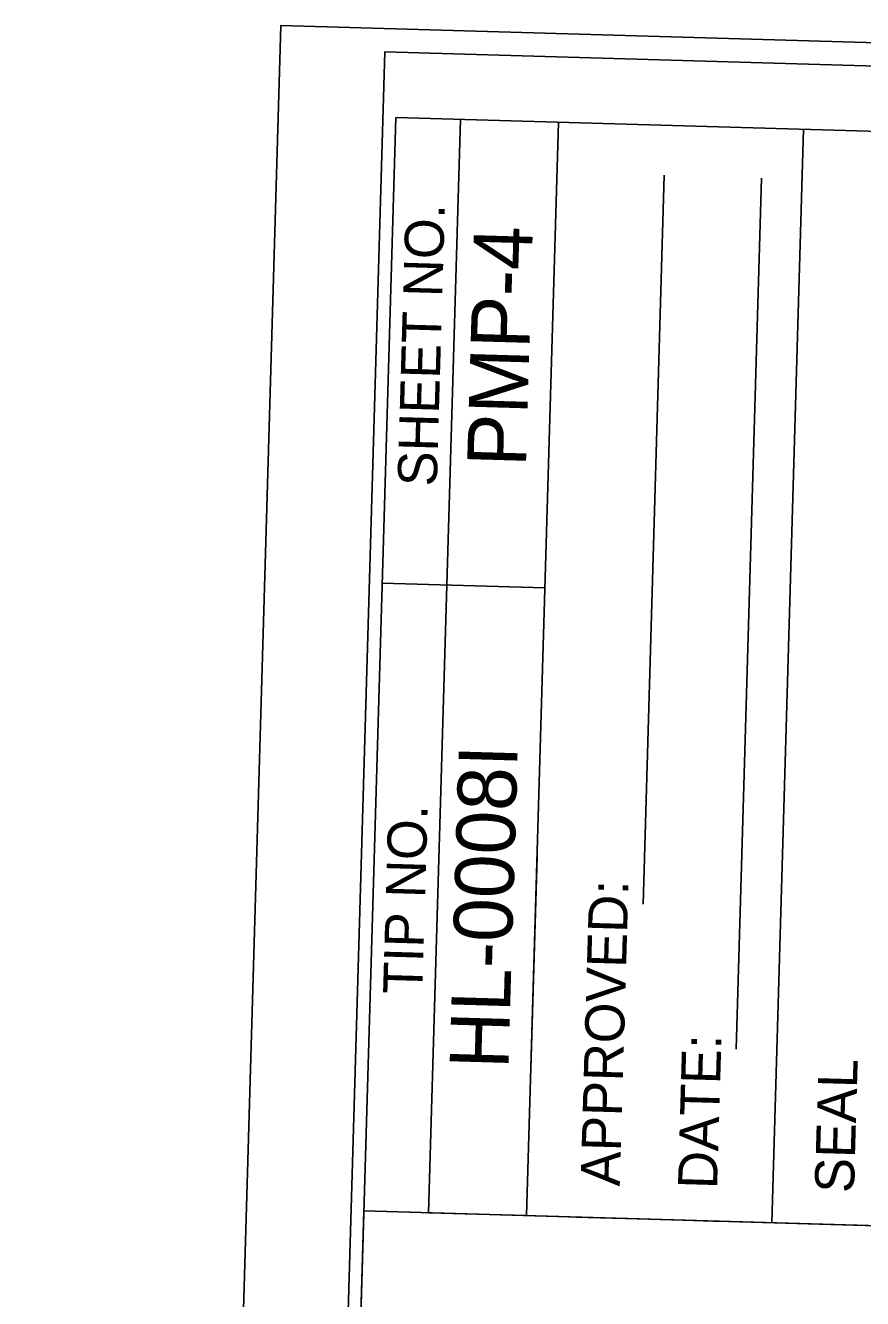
# Model space of a CAD drawing. Extents: x 2097002 to 2098146, y 685127 to 687089.
# Drawn here: x 2097002.1 to 2097162.3, y 686598.1 to 686842 of the extents above; entities that cross this region are included whole.
import ezdxf

# ---------------------------------------------------------------- set-up
doc = ezdxf.new("R2010")
doc.units = 0
for name, color, linetype in [('Sheet Data Field CELL', 7, 'Continuous'), ('Sheet Layout Plan Border', 7, 'Continuous'), ('Sheet Plan CELL', 7, 'Continuous'), ('Sheet Plot Border Inside CELL', 7, 'Continuous'), ('Sheet Plot Border Outside CELL', 7, 'Continuous'), ('Sheet Title CELL', 7, 'Continuous')]:
    doc.layers.add(name, color=color, linetype=linetype)

msp = doc.modelspace()

# ---------------------------------------------------------------- linework, layer by layer
at = {"layer": 'Sheet Layout Plan Border'}
msp.add_lwpolyline([(2098110.68, 686386.52), (2098090.85, 685704.42), (2097236.93, 685318.96), (2097029.37, 685324.99), (2097061.33, 686424.42), (2097062.77, 686473.85), (2097066.87, 686614.87), (2097306.86, 686607.89), (2097310.43, 686730.69), (2098032.53, 686709.7), (2098023.21, 686389.06)], close=True, dxfattribs=at)
at = {"layer": 'Sheet Plan CELL'}
for p, q in [((2097072.96, 686824.36), (2097029.37, 685324.98)), ((2098122.52, 686793.84), (2097072.96, 686824.36))]:
    msp.add_line(p, q, dxfattribs=at)
at = {"layer": 'Sheet Plot Border Inside CELL'}
msp.add_lwpolyline([(2098076.98, 685140.97), (2098125.38, 686806.22), (2097070.84, 686836.88), (2097022.43, 685171.63)], close=True, dxfattribs=at)
at = {"layer": 'Sheet Plot Border Outside CELL'}
msp.add_lwpolyline([(2098096.59, 685127.4), (2098145.51, 686810.14), (2097050.98, 686841.96), (2097002.06, 685159.22)], close=True, dxfattribs=at)
at = {"layer": 'Sheet Title CELL'}
for p, q in [((2097082.75, 686734.77), (2097085.34, 686824)), ((2097104.11, 686823.45), (2097098.02, 686613.96)), ((2097144.95, 686612.6), (2097151.04, 686822.09)), ((2097120.31, 686673.66), (2097124.37, 686813.26)), ((2097138.16, 686645.85), (2097143.01, 686812.71)), ((2097101.53, 686734.22), (2097070.37, 686735.13)), ((2097079.25, 686614.51), (2097082.75, 686734.77)), ((2097100.03, 686682.78), (2097098.85, 686642.12)), ((2097066.87, 686614.87), (2097256.01, 686609.37)), ((2097098.02, 686613.96), (2097079.25, 686614.51)), ((2097116.8, 686613.41), (2097107.42, 686613.69)), ((2097135.56, 686612.87), (2097126.19, 686613.14))]:
    msp.add_line(p, q, dxfattribs=at)

# ---------------------------------------------------------------- texts
at = {"layer": 'Sheet Data Field CELL'}
for s, height, p in [('SHEET NO.', 7.512, (2097080.81, 686753.59)), ('PMP-4', 11.268, (2097097.88, 686757.33)), ('HL-0008I', 11.268, (2097094.52, 686641.98)), ('TIP NO.', 7.512, (2097078.03, 686656.32)), ('APPROVED:', 7.512, (2097115.85, 686619.53)), ('DATE:', 7.512, (2097134.49, 686618.99)), ('SEAL', 7.512, (2097160.69, 686618.23))]:
    msp.add_text(s, height=height, rotation=88.3348, dxfattribs=at).set_placement(p)

doc.saveas('drawing.dxf')
